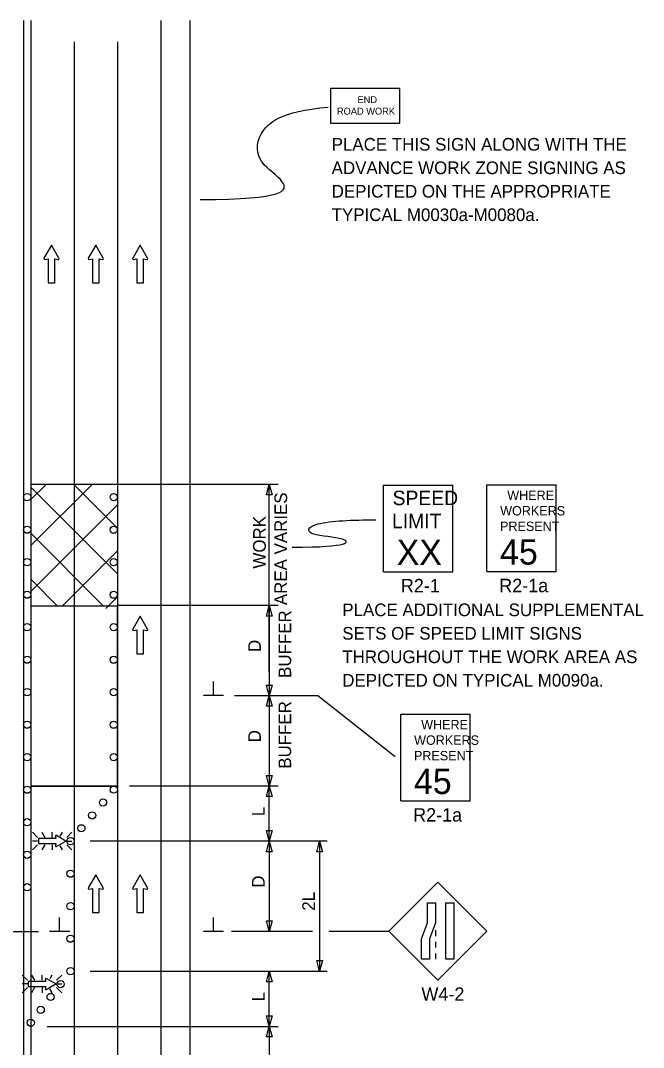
# Model space of a CAD drawing. Extents: x 16727 to 18475, y 5726 to 6927.
# Drawn here: x 17074 to 17419, y 6355 to 6923 of the extents above; entities that cross this region are included whole.
import ezdxf

# ---------------------------------------------------------------- set-up
doc = ezdxf.new("R2010")
doc.units = 0
for name, color, linetype in [('ALI_LEGAL_EX', 7, 'Continuous'), ('MT_SCRATCH_LEVEL_A', 7, 'Continuous'), ('MT_SCRATCH_LEVEL_E', 7, 'Continuous'), ('PAVT_EDGE_EX', 7, 'Continuous'), ('TRAFFIC_SIGNS_PR', 7, 'Continuous'), ('TYPICAL_TEXT_DIMEN_PR', 7, 'Continuous')]:
    doc.layers.add(name, color=color, linetype=linetype)

msp = doc.modelspace()

# ---------------------------------------------------------------- linework, layer by layer
at = {"layer": 'ALI_LEGAL_EX'}
for p, q in [((17104.08, 6911.72), (17104.08, 6082.53)), ((17128.08, 6911.72), (17128.08, 6082.53)), ((17128.08, 6911.72), (17128.08, 6082.53))]:
    msp.add_line(p, q, dxfattribs=at)
for points in [[(17104.08, 6911.72), (17104.08, 6886.72)], [(17128.08, 6911.72), (17128.08, 6886.72)], [(17104.08, 6811.72), (17104.08, 6786.72)], [(17128.08, 6811.72), (17128.08, 6786.72)], [(17104.08, 6711.72), (17104.08, 6686.72)], [(17128.08, 6711.72), (17128.08, 6686.72)], [(17104.08, 6611.72), (17104.08, 6586.72)], [(17128.08, 6611.72), (17128.08, 6586.72)], [(17104.08, 6511.72), (17104.08, 6486.72)], [(17128.08, 6511.72), (17128.08, 6486.72)], [(17104.08, 6411.72), (17104.08, 6386.72)], [(17128.08, 6411.72), (17128.08, 6386.72)]]:
    msp.add_lwpolyline(points, dxfattribs=at)
at = {"layer": 'MT_SCRATCH_LEVEL_A'}
for p, q in [((17134.68, 6666.65), (17080.07, 6666.65)), ((17128.08, 6499.59), (17080.07, 6499.59))]:
    msp.add_line(p, q, dxfattribs=at)
at = {"layer": 'MT_SCRATCH_LEVEL_E'}
for p, q in [((17091.51, 6799.13), (17087.4, 6791.89)), ((17091.51, 6799.13), (17087.4, 6791.89)), ((17095.66, 6791.89), (17091.51, 6799.13)), ((17095.66, 6791.89), (17091.51, 6799.13)), ((17116.04, 6799.13), (17111.93, 6791.89)), ((17116.04, 6799.13), (17111.93, 6791.89)), ((17120.19, 6791.89), (17116.04, 6799.13)), ((17120.19, 6791.89), (17116.04, 6799.13)), ((17140.6, 6799.13), (17136.49, 6791.89)), ((17140.6, 6799.13), (17136.49, 6791.89)), ((17144.75, 6791.89), (17140.6, 6799.13)), ((17144.75, 6791.89), (17140.6, 6799.13)), ((17087.89, 6791.21), (17089.66, 6791.52)), ((17087.89, 6791.21), (17089.66, 6791.52)), ((17089.66, 6791.52), (17089.66, 6778.26)), ((17089.66, 6791.52), (17089.66, 6778.26)), ((17093.4, 6778.26), (17093.4, 6791.52)), ((17093.4, 6791.52), (17095.18, 6791.21)), ((17093.4, 6778.26), (17093.4, 6791.52)), ((17093.4, 6791.52), (17095.18, 6791.21)), ((17112.41, 6791.21), (17114.19, 6791.52)), ((17112.41, 6791.21), (17114.19, 6791.52)), ((17114.19, 6791.52), (17114.19, 6778.26)), ((17114.19, 6791.52), (17114.19, 6778.26)), ((17117.93, 6778.26), (17117.93, 6791.52)), ((17117.93, 6791.52), (17119.71, 6791.21)), ((17117.93, 6778.26), (17117.93, 6791.52)), ((17117.93, 6791.52), (17119.71, 6791.21)), ((17136.97, 6791.21), (17138.75, 6791.52)), ((17136.97, 6791.21), (17138.75, 6791.52)), ((17138.75, 6791.52), (17138.75, 6778.26)), ((17138.75, 6791.52), (17138.75, 6778.26)), ((17142.49, 6778.26), (17142.49, 6791.52)), ((17142.49, 6791.52), (17144.27, 6791.21)), ((17142.49, 6778.26), (17142.49, 6791.52)), ((17142.49, 6791.52), (17144.27, 6791.21)), ((17089.66, 6778.26), (17093.4, 6778.26)), ((17089.66, 6778.26), (17093.4, 6778.26)), ((17114.19, 6778.26), (17117.93, 6778.26)), ((17114.19, 6778.26), (17117.93, 6778.26)), ((17138.75, 6778.26), (17142.49, 6778.26)), ((17138.75, 6778.26), (17142.49, 6778.26)), ((17140.6, 6593.7), (17136.49, 6586.46)), ((17140.6, 6593.7), (17136.49, 6586.46)), ((17144.75, 6586.46), (17140.6, 6593.7)), ((17144.75, 6586.46), (17140.6, 6593.7)), ((17136.97, 6585.78), (17138.75, 6586.1)), ((17136.97, 6585.78), (17138.75, 6586.1)), ((17138.75, 6586.1), (17138.75, 6572.84)), ((17138.75, 6586.1), (17138.75, 6572.84)), ((17142.49, 6572.84), (17142.49, 6586.1)), ((17142.49, 6586.1), (17144.27, 6585.78)), ((17142.49, 6572.84), (17142.49, 6586.1)), ((17142.49, 6586.1), (17144.27, 6585.78)), ((17138.75, 6572.84), (17142.49, 6572.84)), ((17138.75, 6572.84), (17142.49, 6572.84)), ((17116.04, 6450.37), (17111.93, 6443.13)), ((17116.04, 6450.37), (17111.93, 6443.13)), ((17120.19, 6443.13), (17116.04, 6450.37)), ((17120.19, 6443.13), (17116.04, 6450.37)), ((17140.6, 6450.37), (17136.49, 6443.13)), ((17140.6, 6450.37), (17136.49, 6443.13)), ((17144.75, 6443.13), (17140.6, 6450.37)), ((17144.75, 6443.13), (17140.6, 6450.37)), ((17112.41, 6442.44), (17114.19, 6442.76)), ((17112.41, 6442.44), (17114.19, 6442.76)), ((17114.19, 6442.76), (17114.19, 6429.5)), ((17114.19, 6442.76), (17114.19, 6429.5)), ((17117.93, 6429.5), (17117.93, 6442.76)), ((17117.93, 6442.76), (17119.71, 6442.44)), ((17117.93, 6429.5), (17117.93, 6442.76)), ((17117.93, 6442.76), (17119.71, 6442.44)), ((17136.97, 6442.44), (17138.75, 6442.76)), ((17136.97, 6442.44), (17138.75, 6442.76)), ((17138.75, 6442.76), (17138.75, 6429.5)), ((17138.75, 6442.76), (17138.75, 6429.5)), ((17142.49, 6429.5), (17142.49, 6442.76)), ((17142.49, 6442.76), (17144.27, 6442.44)), ((17142.49, 6429.5), (17142.49, 6442.76)), ((17142.49, 6442.76), (17144.27, 6442.44)), ((17114.19, 6429.5), (17117.93, 6429.5)), ((17114.19, 6429.5), (17117.93, 6429.5)), ((17138.75, 6429.5), (17142.49, 6429.5)), ((17138.75, 6429.5), (17142.49, 6429.5))]:
    msp.add_line(p, q, dxfattribs=at)
for centre, start, end in [((17087.81, 6791.66), 150.4248, 279.9638), ((17087.81, 6791.66), 150.4248, 279.9638), ((17095.25, 6791.67), 260.0362, 29.7731), ((17095.25, 6791.67), 260.0362, 29.7731), ((17112.34, 6791.66), 150.4248, 279.9638), ((17112.34, 6791.66), 150.4248, 279.9638), ((17119.78, 6791.67), 260.0362, 29.7731), ((17119.78, 6791.67), 260.0362, 29.7731), ((17136.9, 6791.66), 150.4248, 279.9638), ((17136.9, 6791.66), 150.4248, 279.9638), ((17144.34, 6791.67), 260.0362, 29.7731), ((17144.34, 6791.67), 260.0362, 29.7731), ((17136.9, 6586.24), 150.4248, 279.9638), ((17136.9, 6586.24), 150.4248, 279.9638), ((17144.34, 6586.24), 260.0362, 29.7731), ((17144.34, 6586.24), 260.0362, 29.7731), ((17112.34, 6442.9), 150.4248, 279.9638), ((17112.34, 6442.9), 150.4248, 279.9638), ((17119.78, 6442.9), 260.0362, 29.7731), ((17119.78, 6442.9), 260.0362, 29.7731), ((17136.9, 6442.9), 150.4248, 279.9638), ((17136.9, 6442.9), 150.4248, 279.9638), ((17144.34, 6442.9), 260.0362, 29.7731), ((17144.34, 6442.9), 260.0362, 29.7731)]:
    msp.add_arc(centre, 0.463, start, end, dxfattribs=at)
at = {"layer": 'PAVT_EDGE_EX'}
for p, q in [((17076.08, 6923.5), (17076.08, 6082.53)), ((17080.07, 6923.5), (17080.07, 6082.53)), ((17152.08, 6923.5), (17152.08, 6082.53)), ((17168.08, 6923.5), (17168.08, 6082.53)), ((17080.07, 6723.53), (17080.07, 6608.99)), ((17080.07, 6658.17), (17088.55, 6666.65)), ((17080.07, 6632.71), (17114.01, 6666.65)), ((17128.08, 6642.47), (17103.9, 6666.65)), ((17128.08, 6617.01), (17080.07, 6665.01)), ((17080.07, 6607.26), (17128.08, 6655.26)), ((17120.41, 6599.22), (17080.07, 6639.56)), ((17097.49, 6599.22), (17128.08, 6629.8)), ((17094.96, 6599.22), (17080.07, 6614.1)), ((17121.68, 6597.95), (17128.08, 6604.35)), ((17083.02, 6579.93), (17083.07, 6580.05)), ((17080.07, 6529.02), (17080.07, 6499.59))]:
    msp.add_line(p, q, dxfattribs=at)
msp.add_lwpolyline([(17128.08, 6599.22), (17080.07, 6599.22), (17080.07, 6499.59), (17128.08, 6499.59)], close=True, dxfattribs=at)
at = {"layer": 'TRAFFIC_SIGNS_PR'}
for p, q in [((17275.28, 6666.26), (17313.68, 6666.26)), ((17275.28, 6618.26), (17275.28, 6666.26)), ((17313.68, 6618.26), (17313.68, 6666.26)), ((17332.47, 6666.35), (17370.87, 6666.35)), ((17332.47, 6618.35), (17332.47, 6666.35)), ((17370.87, 6618.35), (17370.87, 6666.35)), ((17275.28, 6618.26), (17313.68, 6618.26)), ((17332.47, 6618.35), (17370.87, 6618.35)), ((17284.83, 6539.32), (17323.23, 6539.32)), ((17284.83, 6491.32), (17284.83, 6539.32)), ((17323.23, 6491.32), (17323.23, 6539.32)), ((17284.83, 6491.32), (17323.23, 6491.32)), ((17083.85, 6471.13), (17081.03, 6473.95)), ((17086.15, 6473.95), (17087.78, 6471.13)), ((17091.94, 6471.13), (17091.94, 6473.95)), ((17097.4, 6473.95), (17096.2, 6471.86)), ((17102.84, 6473.95), (17100.02, 6471.13)), ((17083.85, 6469.1), (17081.03, 6469.1)), ((17083.85, 6467.07), (17081.03, 6464.25)), ((17087.8, 6467.07), (17086.17, 6464.25)), ((17091.94, 6467.07), (17091.94, 6464.25)), ((17096.12, 6466.43), (17097.38, 6464.25)), ((17100.02, 6469.1), (17102.84, 6469.1)), ((17102.84, 6464.25), (17100.02, 6467.07)), ((17305.31, 6446.38), (17278.16, 6419.23)), ((17332.47, 6419.23), (17305.31, 6446.38)), ((17278.16, 6419.23), (17305.31, 6392.07)), ((17304.07, 6419.72), (17304.07, 6416.52)), ((17305.31, 6392.07), (17332.47, 6419.23)), ((17304.07, 6413.32), (17304.07, 6410.12)), ((17304.07, 6406.92), (17304.07, 6403.72)), ((17078.22, 6392.02), (17075.39, 6394.84)), ((17080.51, 6394.84), (17082.14, 6392.02)), ((17086.3, 6392.02), (17086.3, 6394.84)), ((17091.77, 6394.84), (17090.56, 6392.74)), ((17097.2, 6394.84), (17094.39, 6392.02)), ((17078.22, 6389.99), (17075.39, 6389.99)), ((17078.22, 6387.95), (17075.39, 6385.13)), ((17082.17, 6387.95), (17080.54, 6385.13)), ((17086.3, 6387.95), (17086.3, 6385.13)), ((17090.48, 6387.32), (17091.74, 6385.13)), ((17094.39, 6389.99), (17097.2, 6389.99)), ((17097.2, 6385.14), (17094.39, 6387.95))]:
    msp.add_line(p, q, dxfattribs=at)
for points in [[(17245.89, 6866.65), (17284.29, 6866.65), (17284.29, 6885.85), (17245.89, 6885.85)], [(17304.07, 6434.96), (17304.07, 6423.78), (17300.72, 6414.9), (17300.72, 6403.72), (17296.23, 6403.72), (17296.23, 6414.9), (17299.57, 6423.78), (17299.57, 6434.96)], [(17314.2, 6434.96), (17314.2, 6403.72), (17309.71, 6403.72), (17309.71, 6434.96)]]:
    msp.add_lwpolyline(points, close=True, dxfattribs=at)
for points in [[(17093.76, 6471.78), (17093.99, 6470.49), (17084.27, 6470.49), (17084.27, 6467.74), (17093.99, 6467.74), (17093.76, 6466.44)], [(17094.26, 6466.09), (17099.57, 6469.1), (17094.26, 6472.14)], [(17088.13, 6392.67), (17088.36, 6391.37), (17078.63, 6391.37), (17078.63, 6388.63), (17088.36, 6388.63), (17088.12, 6387.32)], [(17088.63, 6386.97), (17093.94, 6389.99), (17088.63, 6393.03)]]:
    msp.add_lwpolyline(points, dxfattribs=at)
for centre in [(17078.08, 6659.54), (17125.98, 6659.54), (17078.08, 6641.54), (17125.98, 6641.54), (17078.08, 6623.54), (17125.98, 6623.54), (17078.08, 6605.54), (17125.98, 6605.54), (17078.08, 6587.54), (17125.98, 6587.54), (17078.08, 6569.54), (17125.98, 6569.54), (17078.08, 6551.54), (17125.98, 6551.54), (17078.08, 6533.54), (17125.98, 6533.54), (17078.08, 6515.54), (17125.98, 6515.54), (17078.08, 6497.54), (17126.07, 6497.59), (17120.07, 6490.45), (17114.07, 6483.31), (17078.08, 6479.54), (17108.07, 6476.17), (17102.07, 6469.03), (17078.08, 6461.54), (17102.07, 6451.03), (17078.08, 6443.54), (17102.07, 6433.03), (17102.07, 6415.03), (17102.07, 6397.03), (17096.58, 6389.9), (17091.08, 6382.77), (17085.58, 6375.64), (17080.08, 6368.52)]:
    msp.add_circle(centre, 2, dxfattribs=at)
for centre, start, end in [((17094.1, 6471.84), 61.4833, 189.9593), ((17094.1, 6466.39), 170.7308, 298.8916), ((17088.46, 6392.73), 61.4833, 189.9593), ((17088.46, 6387.27), 170.7308, 298.8916)]:
    msp.add_arc(centre, 0.341, start, end, dxfattribs=at)
at = {"layer": 'TYPICAL_TEXT_DIMEN_PR'}
for p, q in [((17217.08, 6666.65), (17134.68, 6666.65)), ((17210.51, 6660.78), (17212.08, 6666.65)), ((17212.08, 6562.95), (17212.08, 6666.65)), ((17212.08, 6666.65), (17213.65, 6660.78)), ((17212.08, 6660.78), (17210.51, 6660.78)), ((17213.65, 6660.78), (17212.08, 6660.78)), ((17217.08, 6599.59), (17128.08, 6599.59)), ((17210.51, 6593.73), (17212.08, 6599.59)), ((17212.08, 6599.59), (17212.08, 6549.59)), ((17212.08, 6599.59), (17213.65, 6593.73)), ((17212.08, 6593.73), (17210.51, 6593.73)), ((17213.65, 6593.73), (17212.08, 6593.73)), ((17181.2, 6549.71), (17181.2, 6557.5)), ((17212.08, 6549.59), (17210.51, 6555.46)), ((17210.51, 6555.46), (17212.08, 6555.46)), ((17212.08, 6555.46), (17213.65, 6555.46)), ((17213.65, 6555.46), (17212.08, 6549.59)), ((17186.83, 6549.71), (17175.58, 6549.71)), ((17238.97, 6549.59), (17192.77, 6549.59)), ((17210.51, 6543.73), (17212.08, 6549.59)), ((17212.08, 6549.59), (17212.08, 6499.59)), ((17212.08, 6549.59), (17213.65, 6543.73)), ((17281.68, 6515.76), (17238.97, 6549.59)), ((17212.08, 6543.73), (17210.51, 6543.73)), ((17213.65, 6543.73), (17212.08, 6543.73)), ((17212.08, 6499.59), (17210.51, 6505.46)), ((17210.51, 6505.46), (17212.08, 6505.46)), ((17212.08, 6505.46), (17213.65, 6505.46)), ((17213.65, 6505.46), (17212.08, 6499.59)), ((17217.08, 6499.59), (17134.68, 6499.59)), ((17210.51, 6493.73), (17212.08, 6499.59)), ((17212.08, 6469.03), (17212.08, 6499.59)), ((17212.08, 6499.59), (17213.65, 6493.73)), ((17212.08, 6493.73), (17210.51, 6493.73)), ((17213.65, 6493.73), (17212.08, 6493.73)), ((17212.08, 6469.03), (17210.51, 6474.89)), ((17210.51, 6474.89), (17212.08, 6474.89)), ((17212.08, 6474.89), (17213.65, 6474.89)), ((17213.65, 6474.89), (17212.08, 6469.03)), ((17244.12, 6469.03), (17112.97, 6469.03)), ((17210.51, 6463.17), (17212.08, 6469.03)), ((17212.08, 6469.03), (17212.08, 6419.03)), ((17212.08, 6469.03), (17213.65, 6463.17)), ((17238.31, 6463.17), (17239.88, 6469.03)), ((17239.88, 6469.03), (17241.45, 6463.17)), ((17239.88, 6469.03), (17239.88, 6397.03)), ((17212.08, 6463.17), (17210.51, 6463.17)), ((17213.65, 6463.17), (17212.08, 6463.17)), ((17239.88, 6463.17), (17238.31, 6463.17)), ((17241.45, 6463.17), (17239.88, 6463.17)), ((17096, 6419.03), (17096, 6426.82)), ((17181.2, 6419.03), (17181.2, 6426.82)), ((17212.08, 6419.03), (17210.51, 6424.89)), ((17210.51, 6424.89), (17212.08, 6424.89)), ((17212.08, 6424.89), (17213.65, 6424.89)), ((17213.65, 6424.89), (17212.08, 6419.03)), ((17239.88, 6423.9), (17239.88, 6420.13)), ((16936.74, 6419.03), (17084.27, 6419.03)), ((17101.63, 6419.03), (17090.38, 6419.03)), ((17186.83, 6419.03), (17175.58, 6419.03)), ((17235.97, 6419.03), (17191.08, 6419.03)), ((17278.09, 6419.03), (17244.98, 6419.03)), ((17239.88, 6397.03), (17238.31, 6402.89)), ((17238.31, 6402.89), (17239.88, 6402.89)), ((17239.88, 6402.89), (17241.45, 6402.89)), ((17241.45, 6402.89), (17239.88, 6397.03)), ((17112.97, 6397.03), (17244.12, 6397.03)), ((17210.51, 6391.17), (17212.08, 6397.03)), ((17212.08, 6366.47), (17212.08, 6397.03)), ((17212.08, 6397.03), (17213.65, 6391.17)), ((17212.08, 6391.17), (17210.51, 6391.17)), ((17213.65, 6391.17), (17212.08, 6391.17)), ((17212.08, 6366.47), (17210.51, 6372.33)), ((17210.51, 6372.33), (17212.08, 6372.33)), ((17212.08, 6372.33), (17213.65, 6372.33)), ((17213.65, 6372.33), (17212.08, 6366.47)), ((17089.24, 6366.47), (17217.08, 6366.47)), ((17210.51, 6360.6), (17212.08, 6366.47)), ((17212.08, 6366.47), (17212.08, 6318.47)), ((17212.08, 6366.47), (17213.65, 6360.6)), ((17212.08, 6360.6), (17210.51, 6360.6)), ((17213.65, 6360.6), (17212.08, 6360.6))]:
    msp.add_line(p, q, dxfattribs=at)
for points in [[(17173.74, 6824.35), (17222.2, 6824.35), (17222.2, 6835.11), (17205.42, 6843.87), (17203.99, 6860.68), (17218.35, 6873.16), (17244.68, 6875.56)], [(17224.74, 6631.79), (17257.66, 6631.92), (17256.05, 6637.71), (17232.68, 6637.71), (17232.68, 6645.76), (17258.41, 6647.1), (17270.99, 6646.92)]]:
    msp.add_open_spline(points, degree=3, dxfattribs=at)

# ---------------------------------------------------------------- texts
at = {"layer": 'TRAFFIC_SIGNS_PR'}
for s, height, p in [('END', 3.831, (17260.89, 6877.78)), ('ROAD WORK', 3.831, (17249.5, 6871.4)), ('PLACE THIS SIGN ALONG WITH THE', 7, (17246.6, 6851.46)), ('ADVANCE WORK ZONE SIGNING AS', 7, (17246.6, 6838.46)), ('DEPICTED ON THE APPROPRIATE', 7, (17246.6, 6825.46)), ('TYPICAL M0030a-M0080a.', 7, (17246.6, 6812.46)), ('SPEED', 8, (17280.31, 6655.12)), ('WHERE', 5.2, (17343.78, 6658.03)), ('WORKERS', 5.2, (17339.86, 6649.43)), ('LIMIT', 8, (17279.98, 6642.32)), ('PRESENT', 5.2, (17339.79, 6640.83)), ('XX', 14.031, (17282.58, 6622.02)), ('45', 14.031, (17339.78, 6622.2)), ('R2-1', 7.44, (17284.89, 6606.82)), ('R2-1a', 7.44, (17339.33, 6606.91)), ('PLACE ADDITIONAL SUPPLEMENTAL', 7, (17252.47, 6593.65)), ('SETS OF SPEED LIMIT SIGNS', 7, (17252.47, 6580.65)), ('THROUGHOUT THE WORK AREA AS', 7, (17252.47, 6567.65)), ('DEPICTED ON TYPICAL M0090a.', 7, (17252.47, 6554.65)), ('WHERE', 5.2, (17296.14, 6531)), ('WORKERS', 5.2, (17292.22, 6522.4)), ('PRESENT', 5.2, (17292.15, 6513.8)), ('45', 14.031, (17292.14, 6495.18)), ('R2-1a', 7.44, (17291.69, 6479.88)), ('W4-2', 7.44, (17296.27, 6380.63))]:
    msp.add_text(s, height=height, dxfattribs=at).set_placement(p)
at = {"layer": 'TYPICAL_TEXT_DIMEN_PR'}
for s, p in [('AREA VARIES', (17221.94, 6599.75)), ('WORK', (17210.14, 6620)), ('BUFFER', (17224.19, 6559.45)), ('D', (17207.42, 6573.81)), ('BUFFER', (17224.19, 6509.16)), ('D', (17207.42, 6523.81)), ('L', (17209.52, 6482.89)), ('D', (17209.52, 6443.25)), ('2L', (17237.32, 6430.53)), ('L', (17209.52, 6380.32))]:
    msp.add_text(s, height=7, rotation=90, dxfattribs=at).set_placement(p)

doc.saveas('drawing.dxf')
